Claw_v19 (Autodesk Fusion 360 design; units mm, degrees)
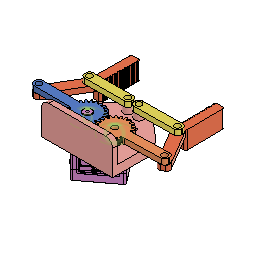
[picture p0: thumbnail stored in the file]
component_insert "Component Insert6"
component_insert "Component Insert7"
component_insert "Component Insert8"
joint "Assemble" alignAngle 0 alignOffsetX 0 alignOffsetY 0 alignOffsetZ 0
component_insert "Component Insert9"
component_insert "Component Insert11"
joint "Assemble" alignAngle 53 alignOffsetX 0 alignOffsetY 0 alignOffsetZ 0
component_insert "Component Insert12"
joint "Assemble" alignAngle -37 (= "-( 90 deg - 53 deg )") alignOffsetX 0 alignOffsetY 0 alignOffsetZ 0
joint "Assemble" alignAngle -97.5 alignOffsetX 0 alignOffsetY 0 alignOffsetZ 0
joint "Assemble" alignAngle 0 alignOffsetX 0 alignOffsetY 0 alignOffsetZ 0
component_insert "Component Insert13"
joint "Assemble" alignAngle -90 alignOffsetX 0 alignOffsetY 0 alignOffsetZ 0
joint "Assemble" alignAngle -90 alignOffsetX 0 alignOffsetY 0 alignOffsetZ 0
component_insert "Component Insert16"
joint "Assemble" alignAngle 0 alignOffsetX 0 alignOffsetY 0 alignOffsetZ 0
joint "Assemble" alignAngle 0 alignOffsetX 0 alignOffsetY 0 alignOffsetZ 0
position "Position1"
